// Mitsubishi GX Works2 project: MD280文本一体机例程   PLC: FX1S

PROGRAM MAIN
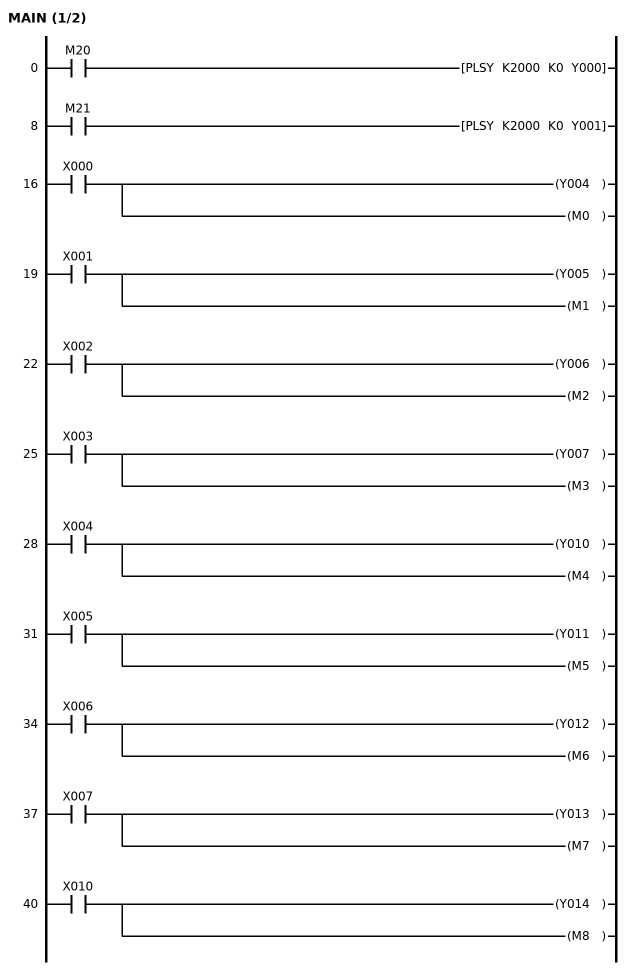
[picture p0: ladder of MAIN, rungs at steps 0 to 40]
0     LD      M20
      PLSY    K2000 K0 Y000
8     LD      M21
      PLSY    K2000 K0 Y001
16    LD      X000
      OUT     Y004
      OUT     M0
19    LD      X001
      OUT     Y005
      OUT     M1
22    LD      X002
      OUT     Y006
      OUT     M2
25    LD      X003
      OUT     Y007
      OUT     M3
28    LD      X004
      OUT     Y010
      OUT     M4
31    LD      X005
      OUT     Y011
      OUT     M5
34    LD      X006
      OUT     Y012
      OUT     M6
37    LD      X007
      OUT     Y013
      OUT     M7
40    LD      X010
      OUT     Y014
      OUT     M8
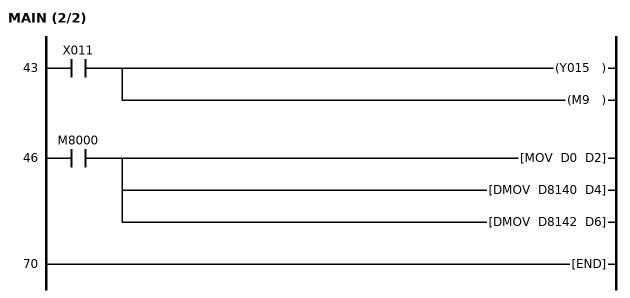
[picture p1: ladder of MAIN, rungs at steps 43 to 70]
43    LD      X011
      OUT     Y015
      OUT     M9
46    LD      M8000
      MOV     D0 D2
      DMOV    D8140 D4
      DMOV    D8142 D6
70    END
END_PROGRAM
